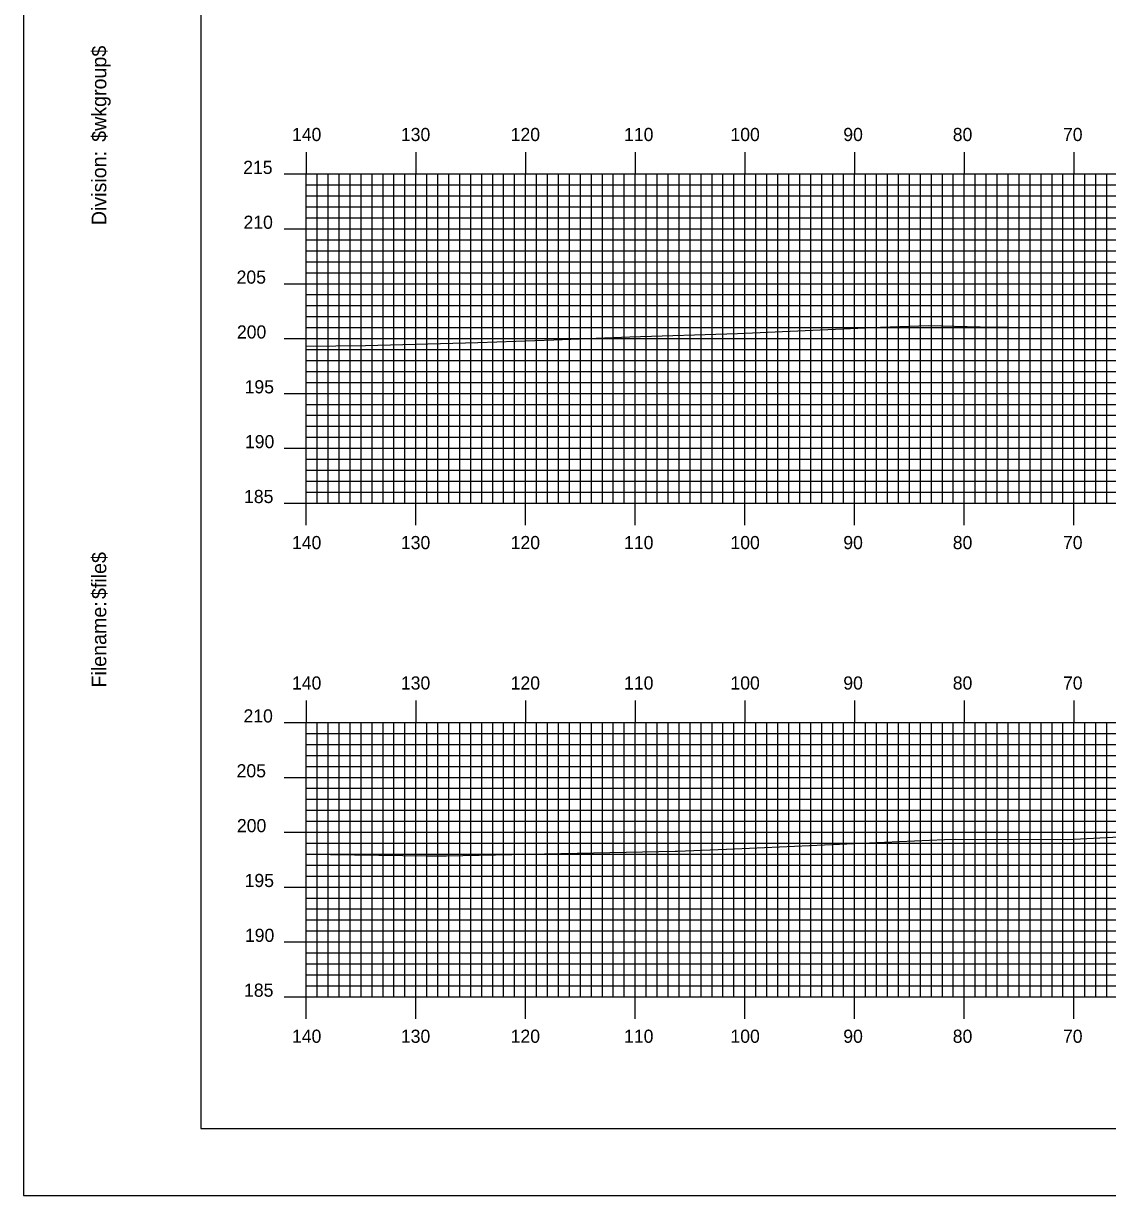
# Model space of a CAD drawing. Extents: x 1799568 to 1799912, y 442591 to 442811.
# Drawn here: x 1799568.2 to 1799667.1, y 442590.5 to 442697.4 of the extents above; entities that cross this region are included whole.
import ezdxf

# ---------------------------------------------------------------- set-up
doc = ezdxf.new("R2010")
doc.units = 0
for name, color, linetype in [('BORDER', 7, 'Continuous'), ('H_V ANNOTATION', 7, 'Continuous'), ('MAJOR', 7, 'Continuous'), ('MINOR', 7, 'Continuous'), ('PLOT BOUNDARY', 7, 'Continuous'), ('S_Roadway_Centerline', 7, 'Continuous')]:
    doc.layers.add(name, color=color, linetype=linetype)

msp = doc.modelspace()

# ---------------------------------------------------------------- linework, layer by layer
at = {"layer": 'BORDER'}
msp.add_lwpolyline([(1799584.41, 442596.67), (1799904.41, 442596.67), (1799904.41, 442806.67), (1799584.41, 442806.67)], close=True, dxfattribs=at)
at = {"layer": 'MAJOR'}
for p, q in [((1799594.01, 442685.67), (1799594.01, 442683.67)), ((1799604.01, 442685.67), (1799604.01, 442683.67)), ((1799614.01, 442685.67), (1799614.01, 442683.67)), ((1799624.01, 442685.67), (1799624.01, 442683.67)), ((1799634.01, 442685.67), (1799634.01, 442683.67)), ((1799644.01, 442685.67), (1799644.01, 442683.67)), ((1799654.01, 442685.67), (1799654.01, 442683.67)), ((1799664.01, 442685.67), (1799664.01, 442683.67)), ((1799592.01, 442683.67), (1799594.01, 442683.67)), ((1799594.01, 442683.67), (1799874.01, 442683.67)), ((1799594.01, 442653.67), (1799594.01, 442683.67)), ((1799594.01, 442653.67), (1799594.01, 442683.67)), ((1799594.01, 442683.67), (1799874.01, 442683.67)), ((1799604.01, 442653.67), (1799604.01, 442683.67)), ((1799614.01, 442653.67), (1799614.01, 442683.67)), ((1799624.01, 442653.67), (1799624.01, 442683.67)), ((1799634.01, 442653.67), (1799634.01, 442683.67)), ((1799644.01, 442653.67), (1799644.01, 442683.67)), ((1799654.01, 442653.67), (1799654.01, 442683.67)), ((1799664.01, 442653.67), (1799664.01, 442683.67)), ((1799592.01, 442678.67), (1799594.01, 442678.67)), ((1799594.01, 442678.67), (1799874.01, 442678.67)), ((1799592.01, 442673.67), (1799594.01, 442673.67)), ((1799594.01, 442673.67), (1799874.01, 442673.67)), ((1799592.01, 442668.67), (1799594.01, 442668.67)), ((1799594.01, 442668.67), (1799874.01, 442668.67)), ((1799592.01, 442663.67), (1799594.01, 442663.67)), ((1799594.01, 442663.67), (1799874.01, 442663.67)), ((1799592.01, 442658.67), (1799594.01, 442658.67)), ((1799594.01, 442658.67), (1799874.01, 442658.67)), ((1799592.01, 442653.67), (1799594.01, 442653.67)), ((1799594.01, 442653.67), (1799874.01, 442653.67)), ((1799594.01, 442653.67), (1799874.01, 442653.67)), ((1799594.01, 442651.66), (1799594.01, 442653.67)), ((1799604.01, 442651.66), (1799604.01, 442653.67)), ((1799614.01, 442651.66), (1799614.01, 442653.67)), ((1799624.01, 442651.66), (1799624.01, 442653.67)), ((1799634.01, 442651.66), (1799634.01, 442653.67)), ((1799644.01, 442651.66), (1799644.01, 442653.67)), ((1799654.01, 442651.66), (1799654.01, 442653.67)), ((1799664.01, 442651.66), (1799664.01, 442653.67)), ((1799594.01, 442635.67), (1799594.01, 442633.67)), ((1799604.01, 442635.67), (1799604.01, 442633.67)), ((1799614.01, 442635.67), (1799614.01, 442633.67)), ((1799624.01, 442635.67), (1799624.01, 442633.67)), ((1799634.01, 442635.67), (1799634.01, 442633.67)), ((1799644.01, 442635.67), (1799644.01, 442633.67)), ((1799654.01, 442635.67), (1799654.01, 442633.67)), ((1799664.01, 442635.67), (1799664.01, 442633.67)), ((1799592.01, 442633.67), (1799594.01, 442633.67)), ((1799594.01, 442633.67), (1799874.01, 442633.67)), ((1799594.01, 442608.67), (1799594.01, 442633.67)), ((1799594.01, 442608.67), (1799594.01, 442633.67)), ((1799594.01, 442633.67), (1799874.01, 442633.67)), ((1799604.01, 442608.67), (1799604.01, 442633.67)), ((1799614.01, 442608.67), (1799614.01, 442633.67)), ((1799624.01, 442608.67), (1799624.01, 442633.67)), ((1799634.01, 442608.67), (1799634.01, 442633.67)), ((1799644.01, 442608.67), (1799644.01, 442633.67)), ((1799654.01, 442608.67), (1799654.01, 442633.67)), ((1799664.01, 442608.67), (1799664.01, 442633.67)), ((1799592.01, 442628.67), (1799594.01, 442628.67)), ((1799594.01, 442628.67), (1799874.01, 442628.67)), ((1799592.01, 442623.67), (1799594.01, 442623.67)), ((1799594.01, 442623.67), (1799874.01, 442623.67)), ((1799592.01, 442618.67), (1799594.01, 442618.67)), ((1799594.01, 442618.67), (1799874.01, 442618.67)), ((1799592.01, 442613.67), (1799594.01, 442613.67)), ((1799594.01, 442613.67), (1799874.01, 442613.67)), ((1799592.01, 442608.67), (1799594.01, 442608.67)), ((1799594.01, 442608.67), (1799874.01, 442608.67)), ((1799594.01, 442608.67), (1799874.01, 442608.67)), ((1799594.01, 442606.66), (1799594.01, 442608.67)), ((1799604.01, 442606.66), (1799604.01, 442608.67)), ((1799614.01, 442606.66), (1799614.01, 442608.67)), ((1799624.01, 442606.66), (1799624.01, 442608.67)), ((1799634.01, 442606.66), (1799634.01, 442608.67)), ((1799644.01, 442606.66), (1799644.01, 442608.67)), ((1799654.01, 442606.66), (1799654.01, 442608.67)), ((1799664.01, 442606.66), (1799664.01, 442608.67))]:
    msp.add_line(p, q, dxfattribs=at)
at = {"layer": 'MINOR'}
for p, q in [((1799595.01, 442653.67), (1799595.01, 442683.67)), ((1799596.01, 442653.67), (1799596.01, 442683.67)), ((1799597.01, 442653.67), (1799597.01, 442683.67)), ((1799598.01, 442653.67), (1799598.01, 442683.67)), ((1799599.01, 442653.67), (1799599.01, 442683.67)), ((1799600.01, 442653.67), (1799600.01, 442683.67)), ((1799601.01, 442653.67), (1799601.01, 442683.67)), ((1799602.01, 442653.67), (1799602.01, 442683.67)), ((1799603.01, 442653.67), (1799603.01, 442683.67)), ((1799605.01, 442653.67), (1799605.01, 442683.67)), ((1799606.01, 442653.67), (1799606.01, 442683.67)), ((1799607.01, 442653.67), (1799607.01, 442683.67)), ((1799608.01, 442653.67), (1799608.01, 442683.67)), ((1799609.01, 442653.67), (1799609.01, 442683.67)), ((1799610.01, 442653.67), (1799610.01, 442683.67)), ((1799611.01, 442653.67), (1799611.01, 442683.67)), ((1799612.01, 442653.67), (1799612.01, 442683.67)), ((1799613.01, 442653.67), (1799613.01, 442683.67)), ((1799615.01, 442653.67), (1799615.01, 442683.67)), ((1799616.01, 442653.67), (1799616.01, 442683.67)), ((1799617.01, 442653.67), (1799617.01, 442683.67)), ((1799618.01, 442653.67), (1799618.01, 442683.67)), ((1799619.01, 442653.67), (1799619.01, 442683.67)), ((1799620.01, 442653.67), (1799620.01, 442683.67)), ((1799621.01, 442653.67), (1799621.01, 442683.67)), ((1799622.01, 442653.67), (1799622.01, 442683.67)), ((1799623.01, 442653.67), (1799623.01, 442683.67)), ((1799625.01, 442653.67), (1799625.01, 442683.67)), ((1799626.01, 442653.67), (1799626.01, 442683.67)), ((1799627.01, 442653.67), (1799627.01, 442683.67)), ((1799628.01, 442653.67), (1799628.01, 442683.67)), ((1799629.01, 442653.67), (1799629.01, 442683.67)), ((1799630.01, 442653.67), (1799630.01, 442683.67)), ((1799631.01, 442653.67), (1799631.01, 442683.67)), ((1799632.01, 442653.67), (1799632.01, 442683.67)), ((1799633.01, 442653.67), (1799633.01, 442683.67)), ((1799635.01, 442653.67), (1799635.01, 442683.67)), ((1799636.01, 442653.67), (1799636.01, 442683.67)), ((1799637.01, 442653.67), (1799637.01, 442683.67)), ((1799638.01, 442653.67), (1799638.01, 442683.67)), ((1799639.01, 442653.67), (1799639.01, 442683.67)), ((1799640.01, 442653.67), (1799640.01, 442683.67)), ((1799641.01, 442653.67), (1799641.01, 442683.67)), ((1799642.01, 442653.67), (1799642.01, 442683.67)), ((1799643.01, 442653.67), (1799643.01, 442683.67)), ((1799645.01, 442653.67), (1799645.01, 442683.67)), ((1799646.01, 442653.67), (1799646.01, 442683.67)), ((1799647.01, 442653.67), (1799647.01, 442683.67)), ((1799648.01, 442653.67), (1799648.01, 442683.67)), ((1799649.01, 442653.67), (1799649.01, 442683.67)), ((1799650.01, 442653.67), (1799650.01, 442683.67)), ((1799651.01, 442653.67), (1799651.01, 442683.67)), ((1799652.01, 442653.67), (1799652.01, 442683.67)), ((1799653.01, 442653.67), (1799653.01, 442683.67)), ((1799655.01, 442653.67), (1799655.01, 442683.67)), ((1799656.01, 442653.67), (1799656.01, 442683.67)), ((1799657.01, 442653.67), (1799657.01, 442683.67)), ((1799658.01, 442653.67), (1799658.01, 442683.67)), ((1799659.01, 442653.67), (1799659.01, 442683.67)), ((1799660.01, 442653.67), (1799660.01, 442683.67)), ((1799661.01, 442653.67), (1799661.01, 442683.67)), ((1799662.01, 442653.67), (1799662.01, 442683.67)), ((1799663.01, 442653.67), (1799663.01, 442683.67)), ((1799665.01, 442653.67), (1799665.01, 442683.67)), ((1799666.01, 442653.67), (1799666.01, 442683.67)), ((1799667.01, 442653.67), (1799667.01, 442683.67)), ((1799594.01, 442682.67), (1799874.01, 442682.67)), ((1799594.01, 442682.67), (1799596.01, 442682.67)), ((1799594.01, 442681.67), (1799874.01, 442681.67)), ((1799594.01, 442681.67), (1799596.01, 442681.67)), ((1799594.01, 442680.67), (1799874.01, 442680.67)), ((1799594.01, 442680.67), (1799596.01, 442680.67)), ((1799594.01, 442679.67), (1799874.01, 442679.67)), ((1799594.01, 442679.67), (1799596.01, 442679.67)), ((1799594.01, 442677.67), (1799874.01, 442677.67)), ((1799594.01, 442677.67), (1799596.01, 442677.67)), ((1799594.01, 442676.67), (1799874.01, 442676.67)), ((1799594.01, 442676.67), (1799596.01, 442676.67)), ((1799594.01, 442675.67), (1799874.01, 442675.67)), ((1799594.01, 442675.67), (1799596.01, 442675.67)), ((1799594.01, 442674.67), (1799874.01, 442674.67)), ((1799594.01, 442674.67), (1799596.01, 442674.67)), ((1799594.01, 442672.67), (1799874.01, 442672.67)), ((1799594.01, 442672.67), (1799596.01, 442672.67)), ((1799594.01, 442671.67), (1799874.01, 442671.67)), ((1799594.01, 442671.67), (1799596.01, 442671.67)), ((1799594.01, 442670.67), (1799874.01, 442670.67)), ((1799594.01, 442670.67), (1799596.01, 442670.67)), ((1799594.01, 442669.67), (1799874.01, 442669.67)), ((1799594.01, 442669.67), (1799596.01, 442669.67)), ((1799594.01, 442667.67), (1799874.01, 442667.67)), ((1799594.01, 442667.67), (1799596.01, 442667.67)), ((1799594.01, 442666.67), (1799874.01, 442666.67)), ((1799594.01, 442666.67), (1799596.01, 442666.67)), ((1799594.01, 442665.67), (1799874.01, 442665.67)), ((1799594.01, 442665.67), (1799596.01, 442665.67)), ((1799594.01, 442664.67), (1799874.01, 442664.67)), ((1799594.01, 442664.67), (1799596.01, 442664.67)), ((1799594.01, 442662.67), (1799874.01, 442662.67)), ((1799594.01, 442662.67), (1799596.01, 442662.67)), ((1799594.01, 442661.67), (1799874.01, 442661.67)), ((1799594.01, 442661.67), (1799596.01, 442661.67)), ((1799594.01, 442660.67), (1799874.01, 442660.67)), ((1799594.01, 442660.67), (1799596.01, 442660.67)), ((1799594.01, 442659.67), (1799874.01, 442659.67)), ((1799594.01, 442659.67), (1799596.01, 442659.67)), ((1799594.01, 442657.67), (1799874.01, 442657.67)), ((1799594.01, 442657.67), (1799596.01, 442657.67)), ((1799594.01, 442656.67), (1799874.01, 442656.67)), ((1799594.01, 442656.67), (1799596.01, 442656.67)), ((1799594.01, 442655.67), (1799874.01, 442655.67)), ((1799594.01, 442655.67), (1799596.01, 442655.67)), ((1799594.01, 442654.67), (1799874.01, 442654.67)), ((1799594.01, 442654.67), (1799596.01, 442654.67)), ((1799595.01, 442608.67), (1799595.01, 442633.67)), ((1799596.01, 442608.67), (1799596.01, 442633.67)), ((1799597.01, 442608.67), (1799597.01, 442633.67)), ((1799598.01, 442608.67), (1799598.01, 442633.67)), ((1799599.01, 442608.67), (1799599.01, 442633.67)), ((1799600.01, 442608.67), (1799600.01, 442633.67)), ((1799601.01, 442608.67), (1799601.01, 442633.67)), ((1799602.01, 442608.67), (1799602.01, 442633.67)), ((1799603.01, 442608.67), (1799603.01, 442633.67)), ((1799605.01, 442608.67), (1799605.01, 442633.67)), ((1799606.01, 442608.67), (1799606.01, 442633.67)), ((1799607.01, 442608.67), (1799607.01, 442633.67)), ((1799608.01, 442608.67), (1799608.01, 442633.67)), ((1799609.01, 442608.67), (1799609.01, 442633.67)), ((1799610.01, 442608.67), (1799610.01, 442633.67)), ((1799611.01, 442608.67), (1799611.01, 442633.67)), ((1799612.01, 442608.67), (1799612.01, 442633.67)), ((1799613.01, 442608.67), (1799613.01, 442633.67)), ((1799615.01, 442608.67), (1799615.01, 442633.67)), ((1799616.01, 442608.67), (1799616.01, 442633.67)), ((1799617.01, 442608.67), (1799617.01, 442633.67)), ((1799618.01, 442608.67), (1799618.01, 442633.67)), ((1799619.01, 442608.67), (1799619.01, 442633.67)), ((1799620.01, 442608.67), (1799620.01, 442633.67)), ((1799621.01, 442608.67), (1799621.01, 442633.67)), ((1799622.01, 442608.67), (1799622.01, 442633.67)), ((1799623.01, 442608.67), (1799623.01, 442633.67)), ((1799625.01, 442608.67), (1799625.01, 442633.67)), ((1799626.01, 442608.67), (1799626.01, 442633.67)), ((1799627.01, 442608.67), (1799627.01, 442633.67)), ((1799628.01, 442608.67), (1799628.01, 442633.67)), ((1799629.01, 442608.67), (1799629.01, 442633.67)), ((1799630.01, 442608.67), (1799630.01, 442633.67)), ((1799631.01, 442608.67), (1799631.01, 442633.67)), ((1799632.01, 442608.67), (1799632.01, 442633.67)), ((1799633.01, 442608.67), (1799633.01, 442633.67)), ((1799635.01, 442608.67), (1799635.01, 442633.67)), ((1799636.01, 442608.67), (1799636.01, 442633.67)), ((1799637.01, 442608.67), (1799637.01, 442633.67)), ((1799638.01, 442608.67), (1799638.01, 442633.67)), ((1799639.01, 442608.67), (1799639.01, 442633.67)), ((1799640.01, 442608.67), (1799640.01, 442633.67)), ((1799641.01, 442608.67), (1799641.01, 442633.67)), ((1799642.01, 442608.67), (1799642.01, 442633.67)), ((1799643.01, 442608.67), (1799643.01, 442633.67)), ((1799645.01, 442608.67), (1799645.01, 442633.67)), ((1799646.01, 442608.67), (1799646.01, 442633.67)), ((1799647.01, 442608.67), (1799647.01, 442633.67)), ((1799648.01, 442608.67), (1799648.01, 442633.67)), ((1799649.01, 442608.67), (1799649.01, 442633.67)), ((1799650.01, 442608.67), (1799650.01, 442633.67)), ((1799651.01, 442608.67), (1799651.01, 442633.67)), ((1799652.01, 442608.67), (1799652.01, 442633.67)), ((1799653.01, 442608.67), (1799653.01, 442633.67)), ((1799655.01, 442608.67), (1799655.01, 442633.67)), ((1799656.01, 442608.67), (1799656.01, 442633.67)), ((1799657.01, 442608.67), (1799657.01, 442633.67)), ((1799658.01, 442608.67), (1799658.01, 442633.67)), ((1799659.01, 442608.67), (1799659.01, 442633.67)), ((1799660.01, 442608.67), (1799660.01, 442633.67)), ((1799661.01, 442608.67), (1799661.01, 442633.67)), ((1799662.01, 442608.67), (1799662.01, 442633.67)), ((1799663.01, 442608.67), (1799663.01, 442633.67)), ((1799665.01, 442608.67), (1799665.01, 442633.67)), ((1799666.01, 442608.67), (1799666.01, 442633.67)), ((1799667.01, 442608.67), (1799667.01, 442633.67)), ((1799594.01, 442632.67), (1799874.01, 442632.67)), ((1799594.01, 442632.67), (1799596.01, 442632.67)), ((1799594.01, 442631.67), (1799874.01, 442631.67)), ((1799594.01, 442631.67), (1799596.01, 442631.67)), ((1799594.01, 442630.67), (1799874.01, 442630.67)), ((1799594.01, 442630.67), (1799596.01, 442630.67)), ((1799594.01, 442629.67), (1799874.01, 442629.67)), ((1799594.01, 442629.67), (1799596.01, 442629.67)), ((1799594.01, 442627.67), (1799874.01, 442627.67)), ((1799594.01, 442627.67), (1799596.01, 442627.67)), ((1799594.01, 442626.67), (1799874.01, 442626.67)), ((1799594.01, 442626.67), (1799596.01, 442626.67)), ((1799594.01, 442625.67), (1799874.01, 442625.67)), ((1799594.01, 442625.67), (1799596.01, 442625.67)), ((1799594.01, 442624.67), (1799874.01, 442624.67)), ((1799594.01, 442624.67), (1799596.01, 442624.67)), ((1799594.01, 442622.67), (1799874.01, 442622.67)), ((1799594.01, 442622.67), (1799596.01, 442622.67)), ((1799594.01, 442621.67), (1799874.01, 442621.67)), ((1799594.01, 442621.67), (1799596.01, 442621.67)), ((1799594.01, 442620.67), (1799874.01, 442620.67)), ((1799594.01, 442620.67), (1799596.01, 442620.67)), ((1799594.01, 442619.67), (1799874.01, 442619.67)), ((1799594.01, 442619.67), (1799596.01, 442619.67)), ((1799594.01, 442617.67), (1799874.01, 442617.67)), ((1799594.01, 442617.67), (1799596.01, 442617.67)), ((1799594.01, 442616.67), (1799874.01, 442616.67)), ((1799594.01, 442616.67), (1799596.01, 442616.67)), ((1799594.01, 442615.67), (1799874.01, 442615.67)), ((1799594.01, 442615.67), (1799596.01, 442615.67)), ((1799594.01, 442614.67), (1799874.01, 442614.67)), ((1799594.01, 442614.67), (1799596.01, 442614.67)), ((1799594.01, 442612.67), (1799874.01, 442612.67)), ((1799594.01, 442612.67), (1799596.01, 442612.67)), ((1799594.01, 442611.67), (1799874.01, 442611.67)), ((1799594.01, 442611.67), (1799596.01, 442611.67)), ((1799594.01, 442610.67), (1799874.01, 442610.67)), ((1799594.01, 442610.67), (1799596.01, 442610.67)), ((1799594.01, 442609.67), (1799874.01, 442609.67)), ((1799594.01, 442609.67), (1799596.01, 442609.67))]:
    msp.add_line(p, q, dxfattribs=at)
at = {"layer": 'PLOT BOUNDARY'}
msp.add_lwpolyline([(1799568.22, 442590.55), (1799908.22, 442590.55), (1799908.22, 442810.55), (1799568.22, 442810.55)], close=True, dxfattribs=at)
at = {"layer": 'S_Roadway_Centerline'}
for points in [[(1799594.01, 442667.96), (1799599.4, 442668.02), (1799609.67, 442668.32), (1799616.58, 442668.56), (1799623.52, 442668.81), (1799633.32, 442669.14), (1799646.38, 442669.71), (1799650.76, 442669.85), (1799655.45, 442669.73), (1799663.02, 442669.64), (1799669.83, 442669.67)], [(1799594.01, 442621.67), (1799605.05, 442621.51), (1799606.81, 442621.52), (1799627.65, 442621.94), (1799627.86, 442621.94), (1799633.06, 442622.16), (1799652.2, 442622.99), (1799653.17, 442623.03), (1799663.42, 442623), (1799674.03, 442623.55)]]:
    msp.add_lwpolyline(points, dxfattribs=at)

# ---------------------------------------------------------------- texts
at = {"layer": 'BORDER'}
for s, p in [('$wkgroup$', (1799575.78, 442686.6)), ('Division:', (1799575.78, 442679)), ('$file$', (1799575.78, 442644.92)), ('Filename:', (1799575.78, 442636.86))]:
    msp.add_text(s, height=1.339, rotation=90, dxfattribs=at).set_placement(p)
at = {"layer": 'H_V ANNOTATION'}
for s, p in [('140', (1799592.71, 442686.67)), ('130', (1799602.64, 442686.67)), ('120', (1799612.65, 442686.67)), ('110', (1799622.99, 442686.67)), ('100', (1799632.69, 442686.67)), ('90', (1799642.98, 442686.67)), ('80', (1799652.96, 442686.67)), ('70', (1799663.01, 442686.67)), ('215', (1799588.26, 442683.67)), ('210', (1799588.29, 442678.67)), ('205', (1799587.66, 442673.67)), ('200', (1799587.69, 442668.67)), ('195', (1799588.39, 442663.67)), ('190', (1799588.42, 442658.67)), ('185', (1799588.34, 442653.67)), ('140', (1799592.71, 442649.47)), ('130', (1799602.64, 442649.47)), ('120', (1799612.65, 442649.47)), ('110', (1799622.99, 442649.47)), ('100', (1799632.69, 442649.47)), ('90', (1799642.98, 442649.47)), ('80', (1799652.96, 442649.47)), ('70', (1799663.01, 442649.47)), ('140', (1799592.71, 442636.67)), ('130', (1799602.64, 442636.67)), ('120', (1799612.65, 442636.67)), ('110', (1799622.99, 442636.67)), ('100', (1799632.69, 442636.67)), ('90', (1799642.98, 442636.67)), ('80', (1799652.96, 442636.67)), ('70', (1799663.01, 442636.67)), ('210', (1799588.29, 442633.67)), ('205', (1799587.66, 442628.67)), ('200', (1799587.69, 442623.67)), ('195', (1799588.39, 442618.67)), ('190', (1799588.42, 442613.67)), ('185', (1799588.34, 442608.67)), ('140', (1799592.71, 442604.47)), ('130', (1799602.64, 442604.47)), ('120', (1799612.65, 442604.47)), ('110', (1799622.99, 442604.47)), ('100', (1799632.69, 442604.47)), ('90', (1799642.98, 442604.47)), ('80', (1799652.96, 442604.47)), ('70', (1799663.01, 442604.47))]:
    msp.add_text(s, height=1.2, dxfattribs=at).set_placement(p)
at = {"layer": 'MAJOR'}
for p in [(1799594, 442653.67), (1799594, 442608.67)]:
    msp.add_text('-', height=0.012, dxfattribs=at).set_placement(p)

doc.saveas('drawing.dxf')
